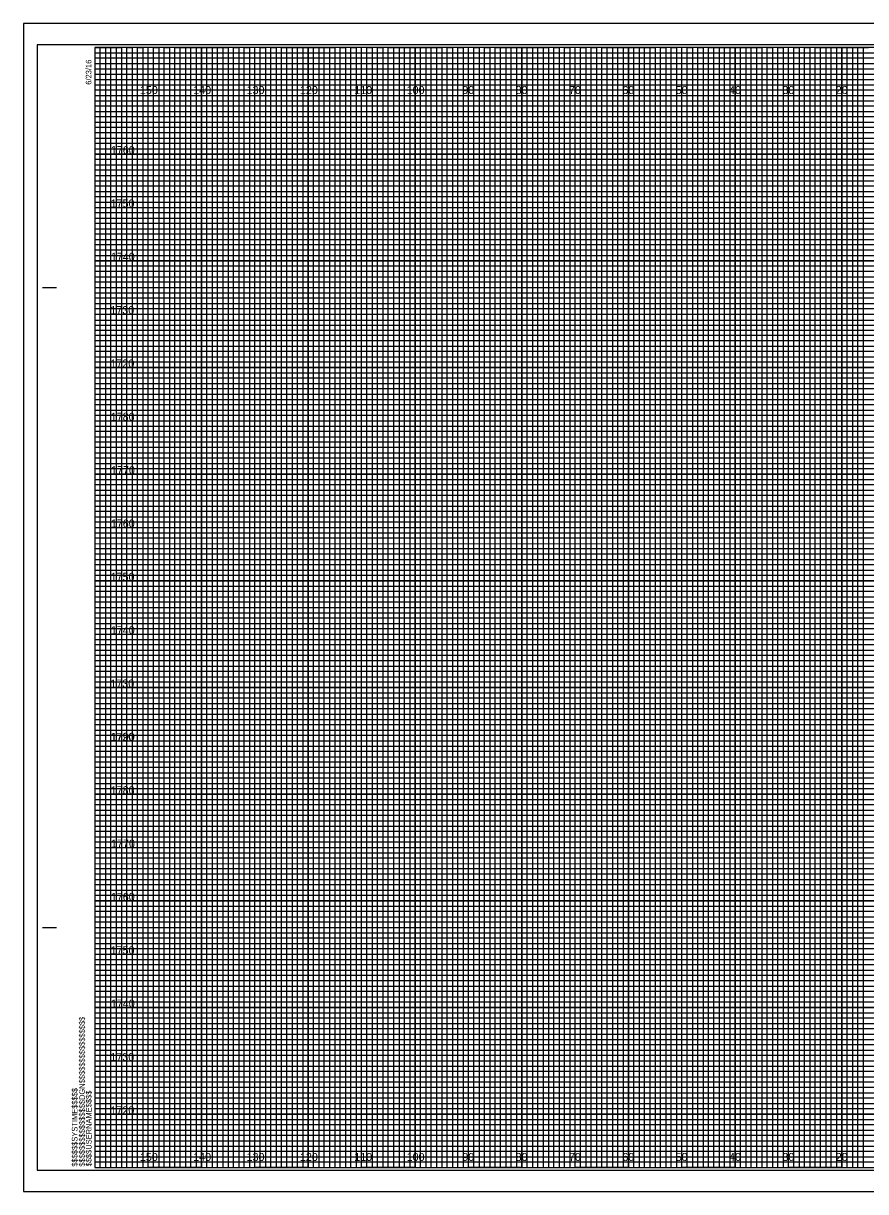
# Model space of a CAD drawing. Extents: x -13 to 323, y -5 to 434.
# Drawn here: x -13.4 to 144.5, y -4.5 to 214.5 of the extents above; entities that cross this region are included whole.
import ezdxf

# ---------------------------------------------------------------- set-up
doc = ezdxf.new("R2010")
doc.units = 0
for name, color, linetype in [('Raster_Level_0', 7, 'Continuous'), ('Scratch_Level_3', 7, 'Continuous'), ('Sheet Cross Section CELL', 7, 'Continuous'), ('Sheet Cross Section Grid Major CELL', 7, 'Continuous'), ('Sheet Cross Section Grid Middle CELL', 7, 'Continuous'), ('Sheet Cross Section Grid Minor 1 CELL', 7, 'Continuous'), ('Sheet Cross Section Grid Minor 2 CELL', 7, 'Continuous'), ('Sheet Cutting Line CELL', 7, 'Continuous'), ('Sheet DOT Grid CELL', 7, 'Continuous'), ('Sheet Plot Border Inside CELL', 7, 'Continuous'), ('Sheet Plot Border Outside CELL', 7, 'Continuous')]:
    doc.layers.add(name, color=color, linetype=linetype)

msp = doc.modelspace()

# ---------------------------------------------------------------- linework, layer by layer
at = {"layer": 'Sheet Cross Section CELL'}
for p, q in [((-9.8, 165), (-7.3, 165)), ((-9.7, 165), (-7.2, 165)), ((-9.8, 45), (-7.3, 45)), ((-9.7, 45), (-7.2, 45)), ((0, 0), (0, 0)), ((0, 0), (0, 0)), ((0, 0), (0, 0)), ((0, 0), (0, 0)), ((0, 0), (0, 0)), ((0, 0), (0, 0)), ((0, 0), (0, 0))]:
    msp.add_line(p, q, dxfattribs=at)
msp.add_lwpolyline([(320, 210), (0, 210), (0, 0), (320, 0)], close=True, dxfattribs=at)
at = {"layer": 'Sheet Cross Section Grid Major CELL'}
for p, q in [((10, 210), (0, 210)), ((10, 0), (10, 210)), ((30, 210), (20, 210)), ((20, 210), (20, 0)), ((30, 0), (30, 210)), ((50, 210), (40, 210)), ((40, 210), (40, 0)), ((50, 0), (50, 210)), ((70, 210), (60, 210)), ((60, 210), (60, 0)), ((70, 0), (70, 210)), ((90, 210), (80, 210)), ((80, 210), (80, 0)), ((90, 0), (90, 210)), ((110, 210), (100, 210)), ((100, 210), (100, 0)), ((110, 0), (110, 210)), ((130, 210), (120, 210)), ((120, 210), (120, 0)), ((130, 0), (130, 210)), ((150, 210), (140, 210)), ((140, 210), (140, 0)), ((20, 0), (10, 0)), ((40, 0), (30, 0)), ((60, 0), (50, 0)), ((80, 0), (70, 0)), ((100, 0), (90, 0)), ((120, 0), (110, 0)), ((140, 0), (130, 0))]:
    msp.add_line(p, q, dxfattribs=at)
for points in [[(0, 200), (320, 200), (320, 190), (0, 190)], [(0, 180), (320, 180), (320, 170), (0, 170)], [(0, 160), (320, 160), (320, 150), (0, 150)], [(0, 140), (320, 140), (320, 130), (0, 130)], [(0, 120), (320, 120), (320, 110), (0, 110)], [(0, 100), (320, 100), (320, 90), (0, 90)], [(0, 80), (320, 80), (320, 70), (0, 70)], [(0, 60), (320, 60), (320, 50), (0, 50)], [(0, 40), (320, 40), (320, 30), (0, 30)], [(0, 20), (320, 20), (320, 10), (0, 10)]]:
    msp.add_lwpolyline(points, dxfattribs=at)
at = {"layer": 'Sheet Cross Section Grid Middle CELL'}
for points in [[(0, 210), (5, 210), (5, 0), (15, 0), (15, 210), (25, 210), (25, 0), (35, 0), (35, 210), (45, 210), (45, 0), (55, 0), (55, 210), (65, 210), (65, 0), (75, 0), (75, 210), (85, 210), (85, 0), (95, 0), (95, 210), (105, 210), (105, 0), (115, 0), (115, 210), (125, 210), (125, 0), (135, 0), (135, 210), (145, 210)], [(0, 205), (275, 205)], [(0, 185), (320, 185), (320, 195), (0, 195)], [(0, 165), (320, 165), (320, 175), (0, 175)], [(0, 145), (320, 145), (320, 155), (0, 155)], [(0, 125), (320, 125), (320, 135), (0, 135)], [(0, 105), (320, 105), (320, 115), (0, 115)], [(0, 85), (320, 85), (320, 95), (0, 95)], [(0, 65), (320, 65), (320, 75), (0, 75)], [(0, 45), (320, 45), (320, 55), (0, 55)], [(0, 25), (320, 25), (320, 35), (0, 35)], [(0, 5), (320, 5), (320, 15), (0, 15)]]:
    msp.add_lwpolyline(points, dxfattribs=at)
at = {"layer": 'Sheet Cross Section Grid Minor 1 CELL'}
for p, q in [((0, 209), (260, 209)), ((260, 207.98), (0, 207.98)), ((0, 207.98), (0, 207)), ((0, 207), (260, 207)), ((260, 205.89), (0, 205.89)), ((0, 205.89), (0, 204)), ((0, 204), (320, 204))]:
    msp.add_line(p, q, dxfattribs=at)
for points in [[(0, 203), (270, 203), (320, 203), (320, 202), (0, 202)], [(0, 201), (320, 201), (320, 199), (0, 199)], [(0, 198), (320, 198), (320, 197), (0, 196.98)], [(0, 196), (320, 196), (320, 194), (0, 194)], [(0, 193), (320, 193), (320, 192), (0, 192)], [(0, 191), (320, 191), (320, 189), (0, 189)], [(0, 188), (320, 188), (320, 187), (0, 187)], [(0, 186), (320, 186), (320, 184), (0, 184)], [(0, 183), (320, 183), (320, 182), (0, 182)], [(0, 181), (320, 181), (320, 179), (0, 179)], [(0, 178), (320, 178), (320, 177), (0, 177)], [(0, 176), (320, 176), (320, 173.95), (320, 173), (320, 172), (0, 172)], [(0, 174), (320, 174), (320, 173), (0, 173)], [(0, 171), (320, 171), (320, 169), (0, 169.03)], [(0, 169.03), (320, 169), (320, 168), (0, 168)], [(0, 167), (320, 167), (320, 166), (0, 166)], [(0, 164), (320, 164), (320, 163), (0, 163)], [(0, 162), (320, 162), (320, 161), (0, 161)], [(-0.07, 158.89), (320, 158.89), (320, 157.88), (-0.07, 157.88)], [(0, 157), (320, 157), (320, 156), (0, 156)], [(0, 154), (320, 154), (320, 153), (0, 153)], [(0, 152), (320, 152), (320, 151), (0, 151)], [(0, 149), (320, 149), (320, 148), (0, 148)], [(0, 147), (320, 147), (320, 146), (0, 146)], [(0, 144), (320, 144), (320, 143), (0, 143)], [(0, 142), (320, 142), (320, 141), (0, 141)], [(0, 139), (320, 139), (319.99, 137.98), (0, 138)], [(0, 137), (320, 137), (320, 136), (0, 136)], [(0, 134), (320, 134), (320, 133), (0, 133)], [(0, 132), (320, 132), (320, 131), (0, 131)], [(0, 129), (320, 129), (320, 128), (0, 128)], [(0, 127), (320, 127), (320, 126), (0, 126)], [(0, 124), (320, 124), (320, 123), (0, 123)], [(0, 122), (320, 122), (320, 121), (0, 121)], [(0, 119), (320, 119), (320, 118), (0, 118)], [(0, 116.99), (320.07, 116.91), (320, 116), (0, 116)], [(0, 114), (320, 114), (320, 113), (0, 113)], [(0, 112), (320, 112), (320, 111), (0, 111)], [(0, 109), (320, 109), (320, 108), (0, 108)], [(0, 107), (320, 107), (320, 106), (0, 106)], [(0, 104), (320, 104), (320, 103), (0, 103)], [(0, 102), (320, 102), (320, 101), (0, 101)], [(0, 99), (320, 99), (320, 98), (0, 98)], [(0, 97), (320, 97), (320, 96), (0, 96)], [(0, 94), (320, 94), (320, 93), (0, 93)], [(0, 92), (320, 92), (320, 91), (0, 91)], [(0, 89), (320, 89), (320, 88), (0, 88)], [(0, 87), (320, 87), (320, 86), (0, 86)], [(0, 84), (320, 84), (320, 83), (0, 83)], [(0, 82), (320, 82), (320, 81), (0, 81)], [(0, 79), (320, 79), (319.99, 77.98), (0, 78)], [(0, 77), (320, 77), (320, 76), (0, 76)], [(0, 74), (320, 74), (320, 73), (0, 73)], [(0, 72), (320, 72), (320, 71), (0, 71)], [(0, 69), (320, 69), (320, 68), (0, 68)], [(0, 67), (320, 67), (320, 66), (0, 66)], [(0, 64), (320, 64), (320, 63), (0, 63)], [(0, 62), (320, 62), (320, 61), (0, 61)], [(0, 59), (320, 59), (320, 58), (0, 58)], [(0, 56.99), (320.07, 56.91), (320, 56), (0, 56)], [(0, 54), (320, 54), (320, 53), (0, 53)], [(0, 52), (320, 52), (320, 51), (0, 51)], [(0, 49), (320, 49), (320, 48), (0, 48)], [(0, 47), (320, 47), (320, 46), (0, 46)], [(0, 44), (320, 44), (320, 43), (0, 43)], [(0, 42), (320, 42), (320, 41), (0, 41)], [(0, 39), (320, 39), (320, 38), (0, 38)], [(0, 37), (320, 37), (320, 36), (0, 36)], [(0, 34), (320, 34), (320, 33), (0, 33)], [(0, 32), (320, 32), (320, 31), (0, 31)], [(0, 29), (320, 29), (320, 28), (0, 28)], [(0, 27), (320, 27), (320, 26), (0, 26)], [(0, 24), (320, 24), (320, 23), (0, 23)], [(0, 22), (320, 22), (320, 21), (0, 21)], [(0, 19), (320, 19), (320, 18), (0, 18)], [(0, 17), (320, 17), (320, 16), (0, 16)], [(0, 14), (320, 14), (320, 13), (0, 13)], [(0, 12), (320, 12), (320, 11), (0, 11)], [(0, 9), (320, 9), (320, 8), (0, 8)], [(0, 7), (320, 7), (320, 6), (0, 6)], [(0, 4), (320, 4), (320, 3), (0, 3)], [(0, 2), (320, 2), (320, 1), (0, 1)]]:
    msp.add_lwpolyline(points, dxfattribs=at)
at = {"layer": 'Sheet Cross Section Grid Minor 2 CELL'}
for points in [[(0, 0), (1, 0), (1, 210), (2, 210), (2, 0)], [(2, 0), (3, 0), (3, 210), (4, 210), (4, 0)], [(5, 0), (6, 0), (6, 210), (7, 210), (7, 0)], [(7, 0), (8, 0), (8, 210), (9, 210), (9, 0)], [(10, 0), (11, 0), (11, 210), (12, 210), (12, 0)], [(12, 0), (13, 0), (13, 210), (14, 210), (14, 0)], [(15, 0), (16, 0), (16, 210), (17, 210), (17, 0)], [(17, 0), (18, 0), (18, 210), (19, 210), (19, 0)], [(20, 0), (21, 0), (21, 210), (22, 210), (22, 0)], [(22, 0), (23, 0), (23, 210), (24, 210), (24, 0)], [(25, 0), (26, 0), (26, 210), (27, 210), (27, 0)], [(27, 0), (28, 0), (28, 210), (29, 210), (29, 0)], [(30, 0), (31, 0), (31, 210), (32, 210), (32, 0)], [(32, 0), (33, 0), (33, 210), (34, 210), (34, 0)], [(35, 0), (36, 0), (36, 210), (37, 210), (37, 0)], [(37, 0), (38, 0), (38, 210), (39, 210), (39, 0)], [(40, 0), (41, 0), (41, 210), (42, 210), (42, 0)], [(42, 0), (43, 0), (43, 210), (44, 210), (44, 0)], [(45, 0), (46, 0), (46, 210), (47, 210), (47, 0)], [(47, 0), (48, 0), (48, 210), (49, 210), (49, 0)], [(50, 0), (51, 0), (51, 210), (52, 210), (52, 0)], [(52, 0), (53, 0), (53, 210), (54, 210), (54, 0)], [(55, 0), (56, 0), (56, 210), (57, 210), (57, 0)], [(57, 0), (58, 0), (58, 210), (59, 210), (59, 0)], [(60, 0), (61, 0), (61, 210), (62, 210), (62, 0)], [(62, 0), (63, 0), (63, 210), (64, 210), (64, 0)], [(65, 0), (66, 0), (66, 210), (67, 210), (67, 0)], [(67, 0), (68, 0), (68, 210), (69, 210), (69, 0)], [(70, 0), (71, 0), (71, 210), (72, 210), (72, 0)], [(72, 0), (73, 0), (73, 210), (74, 210), (74, 0)], [(75, 0), (76, 0), (76, 210), (77, 210), (77, 0)], [(77, 0), (78, 0), (78, 210), (79, 210), (79, 0)], [(80, 0), (81, 0), (81, 210), (82, 210), (82, 0)], [(82, 0), (83, 0), (83, 210), (84, 210), (84, 0)], [(85, 0), (86, 0), (86, 210), (87, 210), (87, 0)], [(87, 0), (88, 0), (88, 210), (89, 210), (89, 0)], [(90, 0), (91, 0), (91, 210), (92, 210), (92, 0)], [(92, 0), (93, 0), (93, 210), (94, 210), (94, 0)], [(95, 0), (96, 0), (96, 210), (97, 210), (97, 0)], [(97, 0), (98, 0), (98, 210), (99, 210), (99, 0)], [(100, 0), (101, 0), (101, 210), (102, 210), (102, 0)], [(102, 0), (103, 0), (103, 210), (104, 210), (104, 0)], [(105, 0), (106, 0), (106, 210), (107, 210), (107, 0)], [(107, 0), (108, 0), (108, 210), (109, 210), (109, 0)], [(110, 0), (111, 0), (111, 210), (112, 210), (112, 0)], [(112, 0), (113, 0), (113, 210), (114, 210), (114, 0)], [(115, 0), (116, 0), (116, 210), (117, 210), (117, 0)], [(117, 0), (118, 0), (118, 210), (119, 210), (119, 0)], [(120, 0), (121, 0), (121, 210), (122, 210), (122, 0)], [(122, 0), (123, 0), (123, 210), (124, 210), (124, 0)], [(125, 0), (126, 0), (126, 210), (127, 210), (127, 0)], [(127, 0), (128, 0), (128, 210), (129, 210), (129, 0)], [(130, 0), (131, 0), (131, 210), (132, 210), (132, 0)], [(132, 0), (133, 0), (133, 210), (134, 210), (134, 0)], [(135, 0), (136, 0), (136, 210), (137, 210), (137, 0)], [(137, 0), (138, 0), (138, 210), (139, 210), (139, 0)], [(140, 0), (141, 0), (141, 210), (142, 210), (142, 0)], [(142, 0), (143, 0), (143, 210), (144, 210), (144, 0)]]:
    msp.add_lwpolyline(points, dxfattribs=at)
at = {"layer": 'Sheet Cutting Line CELL'}
for p, q in [((323.3, 214.5), (-13.4, 214.5)), ((-13.4, 214.5), (-13.4, -4.5)), ((-13.4, -4.5), (323.3, -4.5))]:
    msp.add_line(p, q, dxfattribs=at)
at = {"layer": 'Sheet DOT Grid CELL'}
for p, q in [((10, 0), (10, 210)), ((20, 0), (20, 210)), ((30, 0), (30, 210)), ((40, 0), (40, 210)), ((50, 0), (50, 210)), ((60, 0), (60, 210)), ((70, 0), (70, 210)), ((80, 0), (80, 210)), ((90, 0), (90, 210)), ((100, 0), (100, 210)), ((110, 0), (110, 210)), ((120, 0), (120, 210)), ((130, 0), (130, 210)), ((140, 0), (140, 210)), ((0, 200), (320, 200)), ((0, 190), (320, 190)), ((0, 180), (320, 180)), ((0, 170), (320, 170)), ((0, 160), (320, 160)), ((0, 150), (320, 150)), ((0, 140), (320, 140)), ((0, 130), (320, 130)), ((0, 120), (320, 120)), ((0, 110), (320, 110)), ((0, 100), (320, 100)), ((0, 90), (320, 90)), ((0, 80), (320, 80)), ((0, 70), (320, 70)), ((0, 60), (320, 60)), ((0, 50), (320, 50)), ((0, 40), (320, 40)), ((0, 30), (320, 30)), ((0, 20), (320, 20)), ((0, 10), (320, 10))]:
    msp.add_line(p, q, dxfattribs=at)
at = {"layer": 'Sheet Plot Border Inside CELL'}
msp.add_lwpolyline([(-10.8, -0.5), (322.4, -0.5), (322.4, 210.5), (-10.8, 210.5)], close=True, dxfattribs=at)
at = {"layer": 'Sheet Plot Border Outside CELL'}
msp.add_lwpolyline([(-13.4, -4.5), (323.3, -4.5), (323.3, 214.5), (-13.4, 214.5)], close=True, dxfattribs=at)

# ---------------------------------------------------------------- texts
at = {"layer": 'Raster_Level_0'}
for s, p in [('150', (8.44, 201.25)), ('140', (18.44, 201.25)), ('130', (28.44, 201.25)), ('120', (38.44, 201.25)), ('110', (48.62, 201.25)), ('100', (58.44, 201.25)), ('90', (68.86, 201.25)), ('80', (78.86, 201.25)), ('70', (88.86, 201.25)), ('60', (98.86, 201.25)), ('50', (108.86, 201.25)), ('40', (118.86, 201.25)), ('30', (128.86, 201.25)), ('20', (138.86, 201.25)), ('150', (8.44, 1.25)), ('140', (18.44, 1.25)), ('130', (28.44, 1.25)), ('120', (38.44, 1.25)), ('110', (48.62, 1.25)), ('100', (58.44, 1.25)), ('90', (68.86, 1.25)), ('80', (78.86, 1.25)), ('70', (88.86, 1.25)), ('60', (98.86, 1.25)), ('50', (108.86, 1.25)), ('40', (118.86, 1.25)), ('30', (128.86, 1.25)), ('20', (138.86, 1.25))]:
    msp.add_text(s, height=1.5, dxfattribs=at).set_placement(p)
at = {"layer": 'Scratch_Level_3'}
for s, p in [('1760', (3, 190)), ('1750', (2.96, 180)), ('1740', (3, 170)), ('1730', (2.92, 160)), ('1720', (2.93, 150)), ('1780', (2.98, 140)), ('1770', (3.04, 130)), ('1760', (3, 120)), ('1750', (2.96, 110)), ('1740', (3, 100)), ('1730', (2.92, 90)), ('1720', (2.93, 80)), ('1790', (3, 80)), ('1780', (2.98, 70)), ('1770', (3.04, 60)), ('1760', (3, 50)), ('1750', (2.96, 40)), ('1740', (3, 30)), ('1730', (2.92, 20)), ('1720', (2.93, 10))]:
    msp.add_text(s, height=1.5, dxfattribs=at).set_placement(p)
at = {"layer": 'Sheet Cross Section CELL'}
for s, p in [('6/23/16', (-0.65, 203)), ('$$$$$$$$$$$$$$$$DGN$$$$$$$$$$$$$$$$', (-1.88, 0.18)), ('$$$$$$SYSTIME$$$$$', (-3.26, 0.18)), ('$$$$USERNAME$$$$', (-0.62, 0.23))]:
    msp.add_text(s, height=1.05, rotation=90, dxfattribs=at).set_placement(p)

doc.saveas('drawing.dxf')
